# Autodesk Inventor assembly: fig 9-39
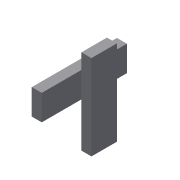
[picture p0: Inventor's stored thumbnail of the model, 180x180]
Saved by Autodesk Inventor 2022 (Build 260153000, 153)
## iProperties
Created: 2013-07
Part Number: fig 9-39
Document SubType Name: Assembly
Designer: CADCIM
Author: CADCIM
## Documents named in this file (2)
- D:\PROJECTS_2021\Resources\Part Files\c09_Inv_2022_prt\fig 9-40.iam
- D:\PROJECTS_2021\Resources\Part Files\c09_Inv_2022_prt\12.ipt
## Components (2 placed, 1 different names)
1. 12:1
2. 12:2
